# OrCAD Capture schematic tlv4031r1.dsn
size A
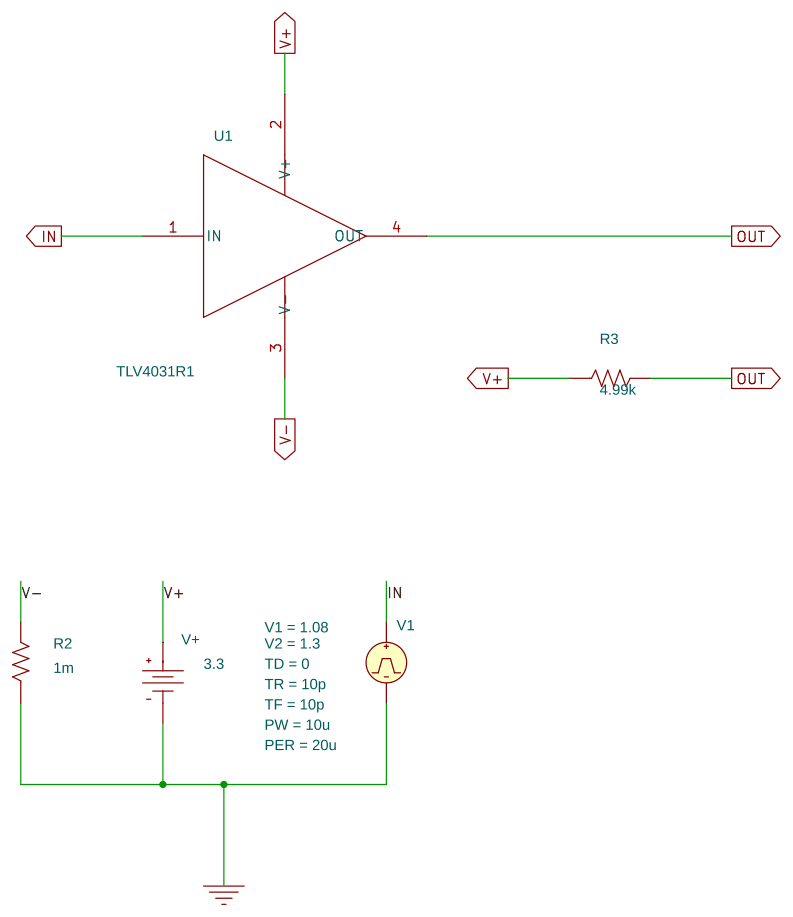
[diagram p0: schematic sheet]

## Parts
R2  1m  [AXRC05]
R3  4.99k  [AXRC05]
U1  TLV4031R1
V1  VPULSE
V+  VDC

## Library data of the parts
R2 R3 = R
U1 = TLV4031R1
V1 = VPULSE: PER: 20u; PW: 10u; TD: 0; TF: 10p; TR: 10p; V1: 1.08; V2: 1.3
V+ = VDC: DC: 3.3

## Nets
0: R2.1 V1.2(-) V+.1(-)
IN: U1.1(IN) V1.1(+)
OUT: R3.2 U1.4(OUT)
V+: R3.1 U1.2(V+) V+.0(+)
V-: R2.2 U1.3(V-)
